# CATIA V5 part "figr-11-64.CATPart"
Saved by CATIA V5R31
Part number: Part1
Bounding box of the stored display mesh (mm): x -54 to 54, y -91.936 to 93.838, z -12.649 to 110.643
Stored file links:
  D:\PROJECTS\Project 2021\US EDITION\CATIA V5 6R 2021\Resources\Part Files\c11_catia_v5_6r2021_prt\figr-11-64.CATPart
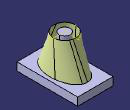
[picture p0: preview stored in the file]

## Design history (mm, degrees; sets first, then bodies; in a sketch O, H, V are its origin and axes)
Set1
  Loft1: Sections (Sketch4; Sketch3)
Body1 (main body)
  Sketch1 on yz-plane, origin (0, 0, 0), H (0, 1, 0), V (0, 0, 1)
    point P1 (93.8379, 11.643)
    line L1 (93.8379, 11.643) -> (93.8379, -12.6487)
    line L2 (93.8379, -12.6487) -> (-91.9362, -12.6487)
    line L3 (-91.9362, -12.6487) -> (-91.9362, 11.643)
    line L4 (-91.9362, 11.643) -> (93.8379, 11.643)
    point P5 (93.8379, 11.643)
    vertical: L1 V, L3 V
    horizontal: L2 H, L4 H
    coincidence: P5 P1
  Pad1: profile Sketch1, direction (1, 0, 0), length 54, mirrored extent
  Sketch2 on face of Pad1, origin (0, 0, 11.643), H (1, 0, 0), V (0, 1, 0)
    circle A1 centre (0, 0) radius 16.7533
    point P1 (16.7533, 0)
    coincidence: A1 P1, P1 H
  Pad2: profile Sketch2, direction (0, 0, 1), length 99
  Sketch3 on face of Pad2, origin (0, 0, 110.643), H (1, 0, 0), V (0, 1, 0)
    point P1 (0, 42.8937)
    point P2 (33.9651, 0)
    projected circle E1 centre (0, 0) radius 16.7533 from edge [face of Pad2 | face of Pad2]
    circle A1 centre (0, 0) radius 33.9651
    point P3 (0, 33.9651)
    coincidence: P1 V, P2 H, A1 P2, A1 P3, P3 V
  Sketch4 on face of Pad1, origin (0, 0, 11.643), H (1, 0, 0), V (0, 1, 0)
    ellipse A1 centre (0, 0) semi-axes 69.9141, 43.1918 rotation 90
    point P1 (0, 69.9141)
    point P2 (43.1918, 0)
    coincidence: P1 V, P2 H, A1 P1, A1 P2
